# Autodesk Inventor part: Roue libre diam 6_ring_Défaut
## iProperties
Shininess: 64.0
Length Units: 11269
Angle Units: 11279
Time Units: 11290
Mass Units: 11283
Length Display Precision: 3
Angle Display Precision: 2
Compacted: True
Part Number: Roue libre diam 6_ring_Défaut
Document SubType Name: Modeling
Created: 2006-01
Material: Par défaut
Designer: riri
Density: 0.0
Volumn: 0.0
Area: 0.0
PropertySet Name: Model Information
Control State: 0
Master: False
Checked Out: False
Author: riri
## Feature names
1. Base1
